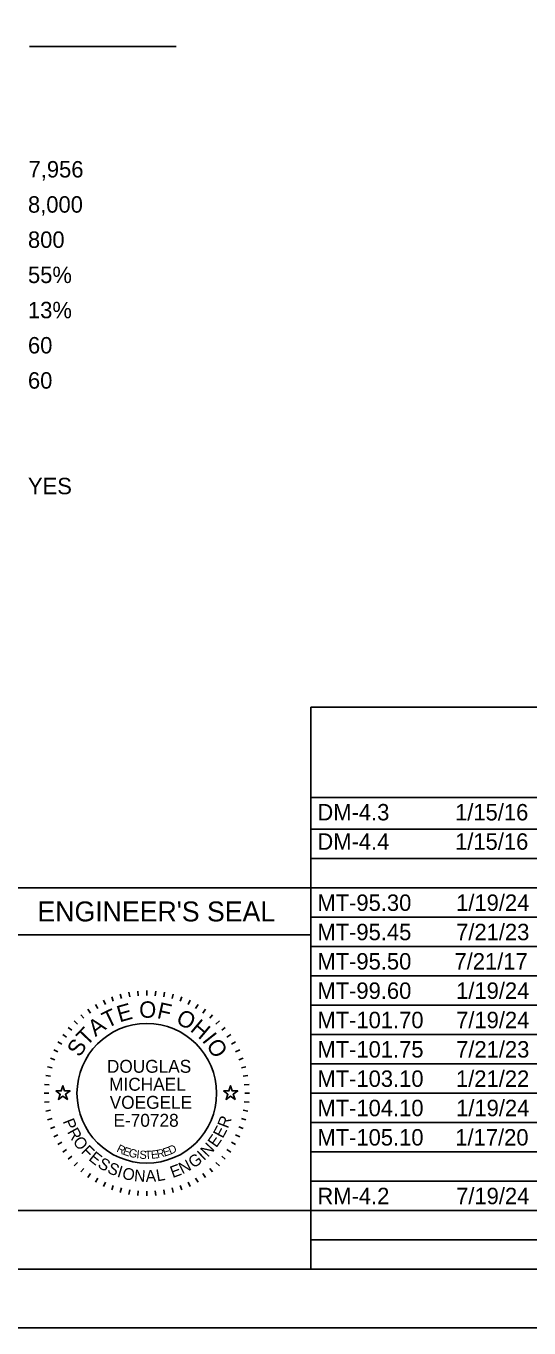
# Model space of a CAD drawing. Extents: x -20.2 to 34, y 0 to 22.
# Drawn here: x 7.72 to 12.01, y 0 to 11.1 of the extents above; entities that cross this region are included whole.
import ezdxf

# ---------------------------------------------------------------- set-up
doc = ezdxf.new("R2010")
doc.units = 0
for name, color, linetype in [('Default', 7, 'Continuous'), ('SH_Border', 7, 'Continuous'), ('SH_Cut_Line', 7, 'Continuous'), ('SH_Data', 7, 'Continuous'), ('SH_Text', 7, 'Continuous')]:
    doc.layers.add(name, color=color, linetype=linetype)

msp = doc.modelspace()

# ---------------------------------------------------------------- linework, layer by layer
at = {"layer": 'Default'}
for points in [[(7.974, 2.02), (8.021, 2.02), (8.035, 2.065), (8.049, 2.02), (8.096, 2.02), (8.058, 1.992), (8.073, 1.948), (8.035, 1.975), (7.997, 1.948), (8.012, 1.992)], [(9.404, 2.02), (9.451, 2.02), (9.465, 2.065), (9.479, 2.02), (9.526, 2.02), (9.488, 1.992), (9.503, 1.948), (9.465, 1.975), (9.427, 1.948), (9.442, 1.992)]]:
    msp.add_lwpolyline(points, close=True, dxfattribs=at)
at = {"layer": 'SH_Border'}
msp.add_lwpolyline([(1.5, 21.5), (33.5, 21.5), (33.5, 0.5), (1.5, 0.5)], close=True, dxfattribs=at)
at = {"layer": 'SH_Cut_Line'}
msp.add_lwpolyline([(0, 0), (34, 0), (34, 22), (0, 22)], close=True, dxfattribs=at)
at = {"layer": 'SH_Data'}
for p, q in [((9, 10.922), (7.75, 10.922)), ((10.15, 5.292), (23.6, 5.292)), ((10.15, 0.5), (10.15, 5.292)), ((10.15, 4.521), (23.6, 4.521)), ((10.15, 4.25), (23.6, 4.25)), ((10.15, 4), (23.6, 4)), ((10.15, 3.75), (7.35, 3.75)), ((10.15, 3.75), (23.6, 3.75)), ((10.15, 0.5), (10.15, 3.75)), ((10.15, 3.5), (23.6, 3.5)), ((10.15, 3.35), (7.35, 3.35)), ((10.15, 3.25), (23.6, 3.25)), ((10.15, 3), (23.6, 3)), ((8.38, 2.793), (8.397, 2.757)), ((8.451, 2.822), (8.464, 2.785)), ((8.524, 2.845), (8.534, 2.807)), ((8.598, 2.862), (8.605, 2.822)), ((8.674, 2.872), (8.677, 2.832)), ((8.75, 2.875), (8.75, 2.835)), ((8.826, 2.872), (8.823, 2.832)), ((8.902, 2.862), (8.895, 2.822)), ((8.976, 2.845), (8.966, 2.807)), ((9.049, 2.822), (9.036, 2.785)), ((9.12, 2.793), (9.103, 2.757)), ((8.188, 2.67), (8.213, 2.64)), ((8.248, 2.717), (8.271, 2.684)), ((8.313, 2.758), (8.333, 2.723)), ((9.187, 2.758), (9.167, 2.723)), ((9.252, 2.717), (9.229, 2.684)), ((9.312, 2.67), (9.287, 2.64)), ((10.15, 2.75), (23.6, 2.75)), ((8.08, 2.562), (8.11, 2.537)), ((8.131, 2.619), (8.16, 2.59)), ((9.369, 2.619), (9.34, 2.59)), ((9.42, 2.562), (9.39, 2.537)), ((8.033, 2.502), (8.066, 2.479)), ((9.467, 2.502), (9.434, 2.479)), ((10.15, 2.5), (23.6, 2.5)), ((7.957, 2.37), (7.993, 2.353)), ((7.992, 2.438), (8.027, 2.418)), ((9.508, 2.438), (9.473, 2.418)), ((9.543, 2.37), (9.507, 2.353)), ((7.905, 2.226), (7.943, 2.216)), ((7.928, 2.299), (7.965, 2.286)), ((9.572, 2.299), (9.535, 2.286)), ((9.595, 2.226), (9.557, 2.216)), ((10.15, 2.25), (23.6, 2.25)), ((7.888, 2.152), (7.928, 2.145)), ((9.612, 2.152), (9.572, 2.145)), ((7.875, 2), (7.915, 2)), ((7.878, 2.076), (7.918, 2.073)), ((9.622, 2.076), (9.582, 2.073)), ((9.625, 2), (9.585, 2)), ((10.15, 2), (23.6, 2)), ((7.878, 1.924), (7.918, 1.927)), ((9.622, 1.924), (9.582, 1.927)), ((7.888, 1.848), (7.928, 1.855)), ((7.905, 1.774), (7.943, 1.784)), ((9.595, 1.774), (9.557, 1.784)), ((9.612, 1.848), (9.572, 1.855)), ((7.928, 1.701), (7.965, 1.714)), ((9.572, 1.701), (9.535, 1.714)), ((10.15, 1.75), (23.6, 1.75)), ((7.957, 1.63), (7.993, 1.647)), ((7.992, 1.563), (8.027, 1.583)), ((9.508, 1.563), (9.473, 1.583)), ((9.543, 1.63), (9.507, 1.647)), ((8.033, 1.498), (8.066, 1.521)), ((8.08, 1.438), (8.11, 1.463)), ((9.42, 1.438), (9.39, 1.463)), ((9.467, 1.498), (9.434, 1.521)), ((10.15, 1.5), (23.6, 1.5)), ((8.131, 1.381), (8.16, 1.41)), ((8.188, 1.33), (8.213, 1.36)), ((9.312, 1.33), (9.287, 1.36)), ((9.369, 1.381), (9.34, 1.41)), ((8.248, 1.283), (8.271, 1.316)), ((8.313, 1.242), (8.333, 1.277)), ((8.38, 1.207), (8.397, 1.243)), ((9.12, 1.207), (9.103, 1.243)), ((9.187, 1.242), (9.167, 1.277)), ((9.252, 1.283), (9.229, 1.316)), ((10.15, 1.25), (23.6, 1.25)), ((8.451, 1.178), (8.464, 1.215)), ((8.524, 1.155), (8.534, 1.193)), ((8.598, 1.138), (8.605, 1.178)), ((8.674, 1.128), (8.677, 1.168)), ((8.75, 1.125), (8.75, 1.165)), ((8.826, 1.128), (8.823, 1.168)), ((8.902, 1.138), (8.895, 1.178)), ((8.976, 1.155), (8.966, 1.193)), ((9.049, 1.178), (9.036, 1.215)), ((10.15, 1), (23.6, 1)), ((10.15, 0.75), (23.6, 0.75)), ((10.15, 0.5), (7.35, 0.5))]:
    msp.add_line(p, q, dxfattribs=at)
msp.add_lwpolyline([(10.15, 0.5), (10.15, 1), (7.35, 1), (7.35, 0.5)], close=True, dxfattribs=at)
msp.add_circle((8.75, 2), 0.595, dxfattribs=at)

# ---------------------------------------------------------------- texts
for s, height, p in [("ENGINEER'S SEAL", 0.17, (7.818, 3.465)), ('DOUGLAS', 0.11, (8.41, 2.175)), ('MICHAEL', 0.11, (8.429, 2.022)), ('VOEGELE', 0.11, (8.434, 1.868)), ('E-70728', 0.11, (8.466, 1.715))]:
    msp.add_text(s, height=height, dxfattribs=at).set_placement(p)
for s, height, rotation, p in [('O', 0.14, 359.7812, (8.685, 2.644)), ('F', 0.14, 347.4362, (8.831, 2.642)), ('T', 0.14, 25.7167, (8.412, 2.552)), ('E', 0.14, 15.7571, (8.518, 2.604)), ('O', 0.14, 332.2586, (8.99, 2.602)), ('T', 0.14, 46.4344, (8.238, 2.396)), ('A', 0.14, 36.4747, (8.313, 2.478)), ('H', 0.14, 319.9136, (9.113, 2.536)), ('S', 0.14, 57.1924, (8.178, 2.301)), ('I', 0.14, 308.367, (9.216, 2.448)), ('O', 0.14, 303.1491, (9.252, 2.409)), ('P', 0.1, 291.494, (8.032, 1.762)), ('R', 0.1, 69.2322, (9.442, 1.695)), ('R', 0.1, 298.7311, (8.069, 1.672)), ('E', 0.1, 61.9951, (9.398, 1.61)), ('O', 0.1, 306.4666, (8.115, 1.588)), ('F', 0.1, 314.7068, (8.184, 1.498)), ('R', 0.07, 334.487, (8.487, 1.505)), ('D', 0.07, 23.3052, (8.951, 1.477)), ('N', 0.1, 47.0224, (9.27, 1.451)), ('E', 0.1, 54.758, (9.343, 1.531)), ('E', 0.1, 321.4393, (8.248, 1.435)), ('S', 0.1, 328.6764, (8.324, 1.375)), ('E', 0.07, 341.04, (8.541, 1.48)), ('G', 0.07, 347.4752, (8.591, 1.462)), ('I', 0.07, 353.7858, (8.659, 1.447)), ('S', 0.07, 356.8926, (8.686, 1.443)), ('T', 0.07, 3.0061, (8.736, 1.439)), ('E', 0.07, 6.0117, (8.789, 1.441)), ('R', 0.07, 11.9184, (8.842, 1.447)), ('E', 0.07, 17.6836, (8.9, 1.46)), ('G', 0.1, 35.0469, (9.148, 1.357)), ('I', 0.1, 43.287, (9.237, 1.421)), ('S', 0.1, 335.9134, (8.406, 1.327)), ('I', 0.1, 343.1505, (8.491, 1.29)), ('O', 0.1, 346.8859, (8.534, 1.275)), ('N', 0.1, 355.1261, (8.639, 1.252)), ('A', 0.1, 2.8617, (8.742, 1.244)), ('L', 0.1, 10.0987, (8.839, 1.249)), ('E', 0.1, 20.0742, (8.971, 1.277)), ('N', 0.1, 27.3113, (9.054, 1.308))]:
    msp.add_text(s, height=height, rotation=rotation, dxfattribs=at).set_placement(p)
at = {"layer": 'SH_Text'}
for s, p in [('7,956', (7.742, 9.806)), ('8,000', (7.737, 9.506)), ('800', (7.737, 9.206)), ('55%', (7.737, 8.906)), ('13%', (7.737, 8.606)), ('60', (7.737, 8.306)), ('60', (7.737, 8.006)), ('YES', (7.737, 7.106)), ('DM-4.3', (10.205, 4.326)), ('1/15/16', (11.379, 4.326)), ('1/15/16', (11.379, 4.076)), ('DM-4.4', (10.205, 4.076)), ('MT-95.30', (10.205, 3.555)), ('1/19/24', (11.388, 3.555)), ('MT-95.45', (10.205, 3.305)), ('7/21/23', (11.388, 3.305)), ('MT-95.50', (10.205, 3.055)), ('7/21/17', (11.374, 3.055)), ('MT-99.60', (10.205, 2.805)), ('1/19/24', (11.388, 2.805)), ('MT-101.70', (10.205, 2.555)), ('7/19/24', (11.388, 2.555)), ('MT-101.75', (10.205, 2.305)), ('7/21/23', (11.388, 2.305)), ('MT-103.10', (10.205, 2.055)), ('1/21/22', (11.387, 2.055)), ('MT-104.10', (10.205, 1.805)), ('1/19/24', (11.388, 1.805)), ('MT-105.10', (10.205, 1.555)), ('1/17/20', (11.381, 1.555)), ('RM-4.2', (10.205, 1.055)), ('7/19/24', (11.388, 1.055))]:
    msp.add_text(s, height=0.14, dxfattribs=at).set_placement(p)

doc.saveas('drawing.dxf')
